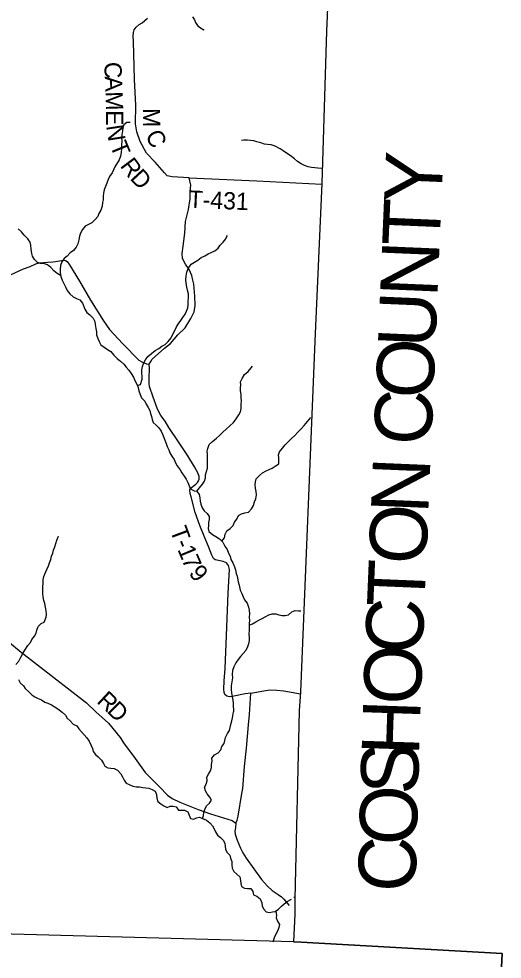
# Model space of a CAD drawing. Extents: x 1759416 to 2214760, y 252598 to 1116833.
# Drawn here: x 2048614 to 2057032, y 815385 to 831751 of the extents above; entities that cross this region are included whole.
import ezdxf

# ---------------------------------------------------------------- set-up
doc = ezdxf.new("R2010")
doc.units = 0
for name, color, linetype in [('GM_X_Adjacent_County', 7, 'Continuous'), ('GM_X_Adjacent_County_Text', 7, 'Continuous'), ('GM_X_County', 7, 'Continuous'), ('GM_X_County_Road', 7, 'Continuous'), ('GM_X_County_Road_Text', 7, 'Continuous'), ('GM_X_Minor_River', 7, 'Continuous'), ('GM_X_Township', 7, 'Continuous'), ('GM_X_Township_Road', 7, 'Continuous'), ('GM_X_Township_Road_Text', 7, 'Continuous')]:
    doc.layers.add(name, color=color, linetype=linetype)

msp = doc.modelspace()

# ---------------------------------------------------------------- linework, layer by layer
at = {"layer": 'GM_X_Adjacent_County'}
for points in [[(2054096, 834376), (2053974, 831534), (2053892, 828885), (2053768, 826142), (2053521, 820038), (2053499, 819706), (2053421, 816435), (2053420, 816169), (2053400, 815687), (2053533, 815684), (2057032, 815483), (2057020, 815247), (2056883, 811617), (2056881, 811520), (2056896, 811456), (2056847, 810908), (2056862, 810765), (2056542, 805719), (2056569, 805221), (2056539, 804360), (2056483, 802899), (2056382, 800495)], [(2056382, 800495), (2056483, 802899), (2056539, 804360), (2056569, 805221), (2056542, 805719), (2056862, 810765), (2056847, 810908), (2056896, 811456), (2056881, 811520), (2056883, 811617), (2057020, 815247), (2057032, 815483), (2053533, 815684), (2053400, 815687), (2048066, 815835), (2047646, 815843), (2042725, 815935), (2041130, 815961), (2039197, 815992), (2038298, 816006), (2034985, 815966), (2034493, 815970), (2032253, 815990), (2029643, 815984)]]:
    msp.add_lwpolyline(points, dxfattribs=at)
at = {"layer": 'GM_X_County'}
msp.add_lwpolyline([(2054096, 834376), (2053974, 831534), (2053892, 828885), (2053768, 826142), (2053521, 820038), (2053499, 819706), (2053421, 816435), (2053420, 816169), (2053400, 815687), (2048066, 815835), (2047646, 815843), (2042725, 815935), (2041130, 815961), (2039197, 815992), (2038298, 816006), (2034985, 815966), (2034493, 815970), (2032253, 815990), (2029643, 815984)], dxfattribs=at)
at = {"layer": 'GM_X_County_Road'}
msp.add_lwpolyline([(2048180, 821120), (2048658, 820728), (2049795, 819847), (2049954, 819691), (2050176, 819493), (2050381, 819243), (2050447, 819135), (2050614, 818917), (2050812, 818633), (2051066, 818384), (2051206, 818241), (2051286, 818182), (2051416, 818118), (2051735, 817988), (2051954, 817915), (2052329, 817796), (2052395, 817752), (2052386, 817672), (2052375, 817613), (2052380, 817562), (2052415, 817454), (2052472, 817317), (2052514, 817236), (2052573, 817146), (2052707, 816957), (2052841, 816774), (2052945, 816654), (2053027, 816582), (2053131, 816512), (2053186, 816470), (2053229, 816432), (2053323, 816317)], dxfattribs=at)
at = {"layer": 'GM_X_Minor_River'}
for points in [[(2051641, 831786), (2051675, 831736), (2051693, 831686), (2051727, 831636), (2051780, 831596), (2051838, 831560), (2051842, 831554)], [(2050555, 829949), (2050497, 829947), (2050445, 829906), (2050423, 829854), (2050417, 829804), (2050411, 829734), (2050405, 829677), (2050409, 829625), (2050401, 829555), (2050401, 829493), (2050397, 829425), (2050383, 829363), (2050359, 829295), (2050287, 829175), (2050261, 829123), (2050239, 829069), (2050193, 829009), (2050169, 828953), (2050145, 828891), (2050122, 828835), (2050102, 828773), (2050088, 828717), (2050082, 828659), (2050082, 828603), (2050074, 828553), (2050066, 828491), (2050040, 828421), (2050010, 828365), (2049988, 828313), (2049942, 828259), (2049888, 828202), (2049768, 828142), (2049724, 828084), (2049686, 828020), (2049672, 827968), (2049662, 827906), (2049642, 827836), (2049614, 827776), (2049566, 827720), (2049510, 827680), (2049458, 827622), (2049402, 827580), (2049362, 827522), (2049342, 827458), (2049336, 827392), (2049334, 827328), (2049344, 827264), (2049368, 827204), (2049400, 827142), (2049428, 827086), (2049457, 827022), (2049503, 826965), (2049561, 826911), (2049617, 826881), (2049678, 826861), (2049726, 826803), (2049748, 826747), (2049764, 826697), (2049798, 826641), (2049852, 826598), (2049907, 826544), (2049939, 826486), (2049945, 826430), (2049953, 826362), (2049969, 826302), (2049969, 826252), (2049988, 826190), (2050012, 826136), (2050044, 826080), (2050100, 826036), (2050160, 825997), (2050216, 825959), (2050271, 825899), (2050329, 825839), (2050383, 825793), (2050443, 825741), (2050482, 825687), (2050532, 825634), (2050570, 825576), (2050614, 825516), (2050636, 825458), (2050669, 825394), (2050695, 825332), (2050705, 825278), (2050729, 825212), (2050753, 825154), (2050810, 825097), (2050834, 825047), (2050868, 824987), (2050894, 824935), (2050906, 824883), (2050922, 824829), (2050934, 824775), (2050953, 824725), (2051009, 824681), (2051055, 824631), (2051091, 824574), (2051117, 824520), (2051139, 824466), (2051158, 824416), (2051182, 824360)], [(2053887, 829147), (2053821, 829152), (2053767, 829160), (2053709, 829162), (2053651, 829176), (2053589, 829200), (2053532, 829228), (2053468, 829269), (2053414, 829313), (2053340, 829371), (2053275, 829415), (2053219, 829453), (2053163, 829487), (2053077, 829536), (2053008, 829556), (2052946, 829564), (2052890, 829572), (2052826, 829590), (2052762, 829610), (2052709, 829626), (2052651, 829633), (2052597, 829639), (2052531, 829637), (2052495, 829631)], [(2049341, 827281), (2049280, 827320), (2049223, 827366), (2049171, 827422), (2049115, 827469), (2049063, 827489), (2048991, 827495), (2048938, 827511), (2048886, 827561), (2048854, 827619), (2048840, 827669), (2048832, 827741), (2048822, 827809), (2048812, 827862), (2048773, 827920), (2048705, 827986), (2048659, 828044), (2048605, 828094)], [(2050681, 825367), (2050731, 825386), (2050761, 825482), (2050761, 825534), (2050757, 825588), (2050757, 825644), (2050768, 825698), (2050786, 825750), (2050818, 825816), (2050860, 825874), (2050927, 825928), (2050991, 825978), (2051053, 826016), (2051105, 826053), (2051165, 826085), (2051217, 826137), (2051269, 826199), (2051293, 826253), (2051325, 826315), (2051355, 826379), (2051389, 826435), (2051437, 826499), (2051469, 826555), (2051509, 826611), (2051535, 826665), (2051555, 826719), (2051563, 826773), (2051565, 826839), (2051567, 826895), (2051567, 826965), (2051552, 827027), (2051540, 827081), (2051528, 827159), (2051524, 827211), (2051530, 827275), (2051538, 827343), (2051562, 827407), (2051616, 827479), (2051672, 827515), (2051730, 827553), (2051790, 827595), (2051852, 827629), (2051910, 827661), (2051966, 827685), (2052025, 827711), (2052087, 827759), (2052119, 827812), (2052175, 827866), (2052219, 827924), (2052243, 827976), (2052237, 827988)], [(2051717, 823530), (2051761, 823586), (2051815, 823654), (2051847, 823706), (2051863, 823760), (2051863, 823816), (2051883, 823872), (2051898, 823930), (2051898, 823994), (2051900, 824048), (2051902, 824110), (2051900, 824174), (2051894, 824224), (2051906, 824274), (2051930, 824342), (2051990, 824394), (2052054, 824452), (2052110, 824500), (2052168, 824556), (2052224, 824612), (2052288, 824668), (2052354, 824724), (2052400, 824792), (2052444, 824858), (2052472, 824912), (2052488, 824972), (2052488, 825042), (2052492, 825104), (2052488, 825156), (2052484, 825212), (2052476, 825276), (2052476, 825328), (2052480, 825380), (2052476, 825432), (2052504, 825492), (2052546, 825560), (2052606, 825612), (2052658, 825676), (2052682, 825704)], [(2052147, 822663), (2052199, 822719), (2052209, 822781), (2052237, 822841), (2052293, 822881), (2052345, 822931), (2052371, 822991), (2052409, 823045), (2052441, 823109), (2052495, 823138), (2052552, 823152), (2052614, 823166), (2052666, 823224), (2052700, 823280), (2052720, 823346), (2052740, 823398), (2052754, 823464), (2052746, 823522), (2052737, 823584), (2052733, 823638), (2052737, 823690), (2052747, 823744), (2052805, 823802), (2052859, 823848), (2052919, 823886), (2052974, 823908), (2053026, 823930), (2053080, 823964), (2053140, 824008), (2053144, 824058), (2053140, 824112), (2053138, 824162), (2053151, 824216), (2053204, 824278), (2053250, 824336), (2053308, 824395), (2053362, 824447), (2053418, 824499), (2053474, 824555), (2053532, 824615), (2053586, 824671), (2053702, 824811)], [(2051182, 824360), (2051196, 824306), (2051228, 824252), (2051246, 824198), (2051280, 824140), (2051321, 824082), (2051345, 824022), (2051373, 823971), (2051423, 823903), (2051455, 823847), (2051494, 823789), (2051528, 823737), (2051556, 823679), (2051580, 823621), (2051604, 823569), (2051666, 823538), (2051717, 823530), (2051755, 823474), (2051767, 823414), (2051773, 823356), (2051785, 823306), (2051809, 823238), (2051840, 823188), (2051892, 823140), (2051930, 823088), (2051930, 823036), (2051920, 822984), (2051916, 822934), (2051914, 822880), (2051926, 822827), (2051987, 822777), (2052047, 822739), (2052109, 822701), (2052167, 822645), (2052204, 822571), (2052242, 822513), (2052268, 822452), (2052292, 822400), (2052308, 822344), (2052342, 822282), (2052371, 822216), (2052385, 822160), (2052399, 822100), (2052417, 822050), (2052437, 821950), (2052453, 821894), (2052470, 821810), (2052498, 821749), (2052524, 821693), (2052544, 821641), (2052588, 821579), (2052614, 821513), (2052627, 821459), (2052633, 821393), (2052627, 821335), (2052631, 821277), (2052625, 821225), (2052623, 821163), (2052623, 821103), (2052619, 821049), (2052623, 820985), (2052625, 820931), (2052615, 820875), (2052596, 820821), (2052566, 820759), (2052519, 820705), (2052477, 820653), (2052437, 820601), (2052395, 820545), (2052357, 820475), (2052335, 820407), (2052332, 820339), (2052334, 820283), (2052326, 820213), (2052310, 820145), (2052310, 820081), (2052318, 820023), (2052330, 819951), (2052344, 819894), (2052348, 819842), (2052349, 819780), (2052351, 819728), (2052354, 819690)], [(2048563, 820511), (2048615, 820569), (2048647, 820643), (2048683, 820703), (2048719, 820761), (2048769, 820843), (2048815, 820895), (2048841, 820949), (2048885, 821007), (2048915, 821061), (2048927, 821111), (2048951, 821175), (2049001, 821230), (2049055, 821250), (2049091, 821338), (2049095, 821388), (2049091, 821446), (2049077, 821511), (2049069, 821577), (2049048, 821627), (2049040, 821693), (2049034, 821749), (2049032, 821807), (2049030, 821867), (2049040, 821929), (2049038, 821985), (2049052, 822047), (2049080, 822113), (2049100, 822167), (2049132, 822233), (2049146, 822283), (2049172, 822341), (2049184, 822397), (2049206, 822449), (2049221, 822505), (2049239, 822563), (2049259, 822621), (2049275, 822679), (2049303, 822745), (2049305, 822747)], [(2052624, 821199), (2052681, 821219), (2052739, 821257), (2052795, 821284), (2052851, 821316), (2052902, 821344), (2052966, 821380), (2053028, 821398), (2053088, 821396), (2053144, 821378), (2053202, 821364), (2053254, 821367), (2053309, 821377), (2053371, 821431), (2053425, 821451), (2053485, 821445), (2053527, 821445)], [(2048607, 820253), (2048640, 820195), (2048696, 820144), (2048726, 820094), (2048788, 820036), (2048839, 819988), (2048891, 819952), (2048949, 819922), (2049007, 819898), (2049067, 819861), (2049120, 819839), (2049184, 819809), (2049258, 819767), (2049316, 819723), (2049370, 819683), (2049370, 819685)], [(2049370, 819683), (2049425, 819631), (2049459, 819578), (2049509, 819536), (2049561, 819476), (2049625, 819444), (2049657, 819393), (2049705, 819341), (2049751, 819289), (2049797, 819235), (2049837, 819178), (2049897, 819054), (2049911, 819000), (2049947, 818946), (2049997, 818909), (2050057, 818849), (2050089, 818793), (2050113, 818743), (2050165, 818716), (2050215, 818710), (2050273, 818702), (2050331, 818676), (2050393, 818610), (2050421, 818559), (2050449, 818503), (2050485, 818447), (2050537, 818423), (2050597, 818397), (2050657, 818386), (2050717, 818382), (2050773, 818376), (2050825, 818368), (2050881, 818360), (2050934, 818339), (2050986, 818307), (2051011, 818249), (2051017, 818189), (2051035, 818129), (2051087, 818086), (2051139, 818054), (2051197, 818026), (2051248, 818048), (2051304, 818050), (2051354, 818036), (2051396, 817981), (2051450, 817979), (2051500, 817979), (2051556, 817949), (2051580, 817893), (2051604, 817832), (2051660, 817824), (2051710, 817846), (2051762, 817858), (2051812, 817836), (2051882, 817805), (2051942, 817757), (2051990, 817705), (2052014, 817653), (2052038, 817599), (2052074, 817544), (2052128, 817504), (2052180, 817450), (2052202, 817400), (2052206, 817350), (2052214, 817299), (2052238, 817247), (2052288, 817195), (2052302, 817141), (2052322, 817083), (2052326, 817027), (2052332, 816968), (2052360, 816912), (2052410, 816864), (2052462, 816818), (2052476, 816757), (2052482, 816703), (2052492, 816653), (2052542, 816621), (2052596, 816617), (2052652, 816615), (2052690, 816562), (2052702, 816508), (2052762, 816482), (2052818, 816434), (2052844, 816368), (2052852, 816313), (2052876, 816259), (2052920, 816207), (2052978, 816199), (2053034, 816207), (2053088, 816214), (2053102, 816154), (2053096, 816102), (2053124, 816036), (2053154, 815986), (2053145, 815934), (2053123, 815882), (2053089, 815820), (2053063, 815756), (2053036, 815684)], [(2051813, 817835), (2051828, 817886), (2051836, 817936), (2051852, 817988), (2051884, 818054), (2051935, 818098), (2051971, 818152), (2051943, 818206), (2051895, 818262), (2051865, 818315), (2051849, 818377), (2051875, 818429), (2051893, 818489), (2051891, 818553), (2051923, 818615), (2051955, 818665), (2051969, 818723), (2051972, 818775), (2051980, 818831), (2051978, 818881), (2052020, 818939), (2052086, 818977), (2052132, 819031), (2052148, 819085), (2052188, 819137), (2052200, 819193), (2052214, 819246), (2052247, 819312), (2052283, 819364), (2052297, 819418), (2052307, 819470), (2052321, 819534), (2052337, 819588), (2052354, 819690)], [(2053078, 816213), (2053134, 816256), (2053188, 816308), (2053238, 816350), (2053290, 816388), (2053362, 816432)], [(2053410, 816460), (2053404, 816458)]]:
    msp.add_lwpolyline(points, dxfattribs=at)
at = {"layer": 'GM_X_Township'}
msp.add_lwpolyline([(2054096, 834376), (2053974, 831534), (2053892, 828885), (2053768, 826142), (2053521, 820038), (2053499, 819706), (2053421, 816435), (2053420, 816169), (2053400, 815687), (2048066, 815835), (2047646, 815843), (2042725, 815935), (2041130, 815961), (2039197, 815992), (2038298, 816006), (2034985, 815966), (2034493, 815970), (2032253, 815990), (2029643, 815984)], dxfattribs=at)
at = {"layer": 'GM_X_Township_Road'}
for points in [[(2050885, 825742), (2050912, 825786), (2050939, 825828), (2051153, 826018), (2051256, 826100), (2051384, 826253), (2051510, 826373), (2051611, 826535), (2051669, 826653), (2051688, 826763), (2051680, 826922), (2051661, 827133), (2051644, 827204), (2051628, 827286), (2051578, 827391), (2051515, 827481), (2051491, 827519), (2051463, 827585), (2051461, 827665), (2051477, 827794), (2051507, 828021), (2051518, 828226), (2051572, 828432), (2051601, 828619), (2051601, 828747), (2051611, 828858), (2051583, 828982), (2051283, 829002), (2051200, 829016), (2051152, 829068), (2050989, 829255), (2050836, 829413), (2050726, 829614), (2050669, 829786), (2050649, 829925), (2050654, 830247), (2050627, 830696), (2050614, 831363), (2050607, 831451), (2050612, 831511), (2050622, 831558), (2050655, 831608), (2050708, 831653), (2050762, 831681), (2050855, 831764)], [(2051583, 828982), (2052761, 828932), (2053892, 828872)], [(2048482, 827303), (2048694, 827397), (2048810, 827443), (2048909, 827484), (2048971, 827504), (2049116, 827517), (2049206, 827521), (2049254, 827528), (2049358, 827543), (2049396, 827549), (2049427, 827545), (2049454, 827529), (2049496, 827470), (2049671, 827186), (2049865, 826856), (2050087, 826494), (2050195, 826346), (2050426, 826094), (2050705, 825810), (2050769, 825774), (2050839, 825749), (2050885, 825742)], [(2052395, 817752), (2052419, 817802), (2052437, 817875), (2052499, 818270), (2052514, 818356), (2052547, 818740), (2052582, 819059), (2052612, 819465), (2052633, 819644), (2052656, 820013), (2052558, 820003), (2052360, 819964), (2052282, 819953), (2052239, 819961), (2052202, 819992), (2052191, 820025), (2052185, 820086), (2052190, 820230), (2052209, 820445), (2052233, 821018), (2052260, 821758), (2052281, 822165), (2052267, 822234), (2052232, 822283), (2052170, 822304), (2052093, 822321), (2052031, 822338), (2052003, 822359), (2051978, 822418), (2051919, 822568), (2051853, 822721), (2051766, 822931), (2051686, 823162), (2051613, 823430), (2051599, 823490), (2051592, 823545), (2051601, 823579), (2051699, 823651), (2051727, 823682), (2051743, 823708), (2051756, 823738), (2051756, 823784), (2051734, 823849), (2051671, 823956), (2051560, 824145), (2051397, 824391), (2051224, 824636), (2051163, 824750), (2051088, 824850), (2051027, 824960), (2050955, 825168), (2050892, 825351), (2050882, 825396), (2050886, 825503), (2050892, 825666), (2050885, 825742)], [(2052656, 820013), (2052880, 820053), (2052983, 820072), (2053108, 820065), (2053232, 820053), (2053519, 820004)]]:
    msp.add_lwpolyline(points, dxfattribs=at)

# ---------------------------------------------------------------- texts
at = {"layer": 'GM_X_Adjacent_County_Text'}
for s, rotation, p in [('Y', 87.5766, (2055972, 828527)), ('T', 87.577, (2055940, 827780)), ('N', 87.5779, (2055903, 826896)), ('U', 87.5766, (2055865, 826013)), ('O', 87.5782, (2055828, 825129)), ('C', 87.5772, (2055794, 824316)), ('N', 87.5787, (2055743, 823129)), ('O', 87.5809, (2055706, 822245)), ('T', 87.6182, (2055675, 821498)), ('C', 87.7239, (2055643, 820685)), ('O', 87.9618, (2055611, 819802)), ('H', 88.1032, (2055582, 818919)), ('S', 88.379, (2055563, 818243)), ('O', 88.5536, (2055541, 817360)), ('C', 88.6176, (2055521, 816546))]:
    msp.add_text(s, height=1000, rotation=rotation, dxfattribs=at).set_placement(p)
at = {"layer": 'GM_X_County_Road_Text'}
for s, rotation, p in [('R', 317.1103, (2049957, 819859)), ('D', 314.7244, (2050135, 819693))]:
    msp.add_text(s, height=300, rotation=rotation, dxfattribs=at).set_placement(p)
at = {"layer": 'GM_X_Township_Road_Text'}
for s, rotation, p in [('C', 272.616, (2050100, 830994)), ('A', 272.5362, (2050111, 830748)), ('M', 271.8197, (2050123, 830485)), ('E', 269.6829, (2050133, 830162)), ('M', 270.7621, (2050774, 830196)), ('N', 278.6395, (2050135, 829887)), ('C', 295.8601, (2050811, 829732)), ('T', 292.5194, (2050196, 829550)), ('R', 306.8078, (2050367, 829191)), ('D', 312.8386, (2050537, 828967)), ('T-431', 357.4742, (2051566, 828466)), ('T', 290.2797, (2051243, 822854)), ('1', 292.5568, (2051373, 822518)), ('-', 292.4429, (2051325, 822632)), ('7', 293.3132, (2051445, 822343)), ('9', 308.2794, (2051562, 822100))]:
    msp.add_text(s, height=300, rotation=rotation, dxfattribs=at).set_placement(p)

doc.saveas('drawing.dxf')
